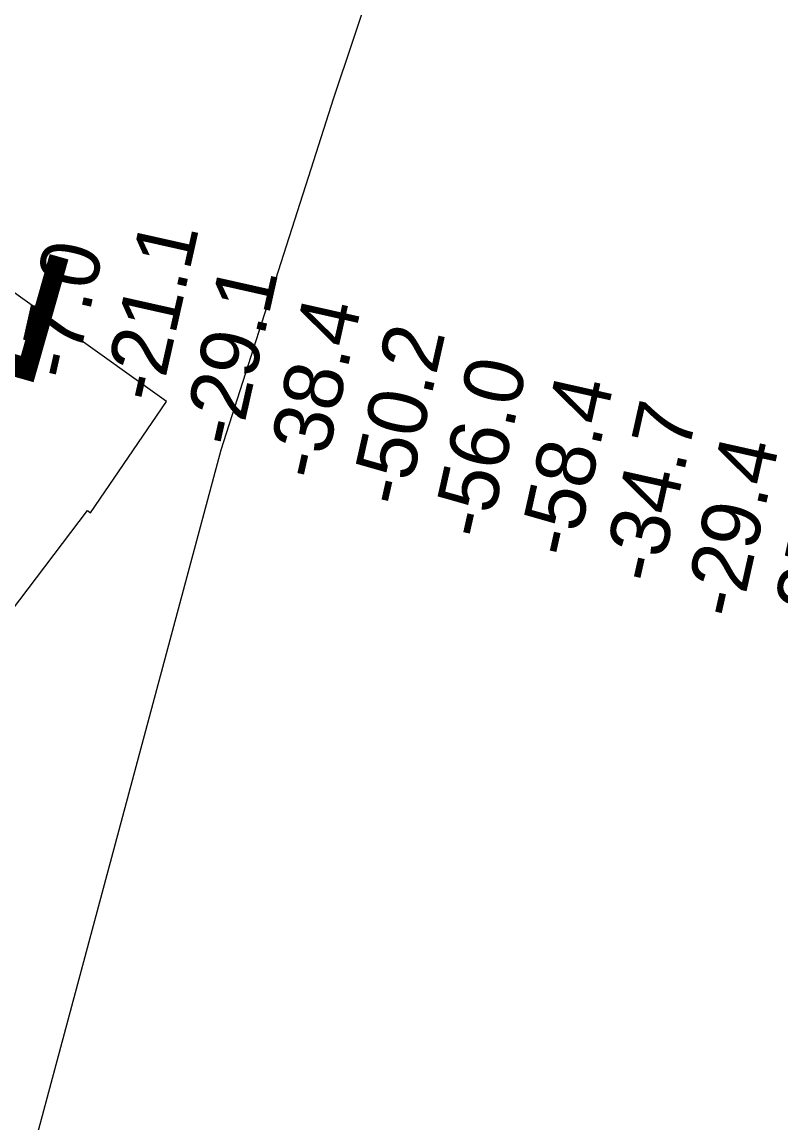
# Model space of a CAD drawing. Extents: x 3148686 to 3186545, y 916144 to 941516.
# Drawn here: x 3161458 to 3162320, y 931737 to 932988 of the extents above; entities that cross this region are included whole.
import ezdxf

# ---------------------------------------------------------------- set-up
doc = ezdxf.new("R2010")
doc.units = 0
for name, color, linetype in [('V-RIVR-IDEN', 7, 'Continuous'), ('V-RIVR-RANG', 7, 'Continuous'), ('V-RRAP-RVMT', 7, 'Continuous'), ('V-TOPO-BNDY', 7, 'Continuous')]:
    doc.layers.add(name, color=color, linetype=linetype)

msp = doc.modelspace()

# ---------------------------------------------------------------- linework, layer by layer
at = {"layer": 'V-RRAP-RVMT'}
for points in [[(3161622.3, 932556.9), (3161286.5, 932796.7), (3161189.9, 932665), (3161193.8, 932661.9), (3161125.7, 932571.6), (3161122.9, 932573.9), (3161032.6, 932445.3), (3161038.2, 932441), (3160875.6, 932206), (3160869.6, 932209.9), (3160786.8, 932086.2), (3160778.4, 932090.9)], [(3161111.2, 931666.9), (3161187.6, 931772.1), (3161181.8, 931776.3), (3161258.1, 931881.5), (3161116.8, 931984.2), (3161135.7, 932013.2), (3161157.5, 931999), (3161313.9, 932234.6), (3161336.3, 932219.4), (3161422.1, 932337.7), (3161446.4, 932319), (3161532.8, 932432.9), (3161536.2, 932430.4), (3161622.3, 932556.9)]]:
    msp.add_lwpolyline(points, dxfattribs=at)
at = {"layer": 'V-TOPO-BNDY'}
msp.add_lwpolyline([(3159006.2, 926311.1), (3159280.9, 926819.7), (3159355.2, 926960.9), (3159433.9, 927110.7), (3159462.3, 927164.6), (3160176.1, 928635), (3160389.8, 929116.4), (3160397.9, 929134.5), (3160404.6, 929149.2), (3160858.7, 930130.4), (3161037.6, 930526.5), (3161154.7, 930785.7), (3161271.9, 931050.2), (3161316.1, 931173.6), (3161356.8, 931287.5), (3161429, 931551), (3161684.4, 932501.7), (3161786.7, 932820.9), (3161812.5, 932901.9), (3162033.7, 933562.9)], dxfattribs=at)

# ---------------------------------------------------------------- texts
at = {"layer": 'V-RIVR-IDEN'}
msp.add_text('V      E      R', height=200, rotation=74.1506, dxfattribs=at).set_placement((3161295.1, 931957.1))
at = {"layer": 'V-RIVR-RANG'}
for s, p in [('-21.1', (3161614.7, 932553.3)), ('-7.0', (3161517.5, 932578.8)), ('-29.1', (3161704.7, 932502.7)), ('-38.4', (3161799.2, 932465.1)), ('-50.2', (3161894.7, 932435.1)), ('-56.0', (3161987.5, 932398)), ('-58.4', (3162085.8, 932377.1)), ('-34.7', (3162181.3, 932347.7)), ('-29.4', (3162273.6, 932307.7)), ('-25.5', (3162370.8, 932282.2))]:
    msp.add_text(s, height=67, rotation=77.3603, dxfattribs=at).set_placement(p)

doc.saveas('drawing.dxf')
